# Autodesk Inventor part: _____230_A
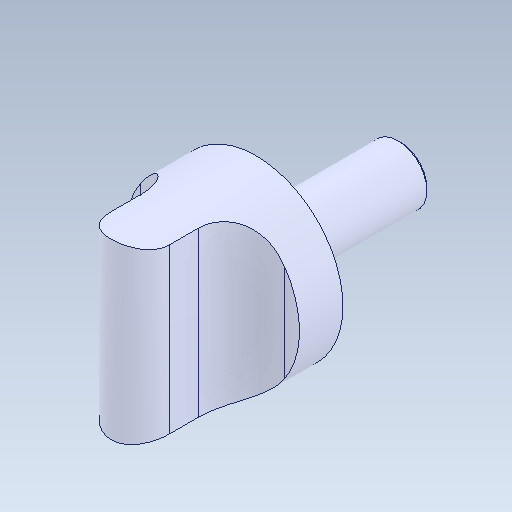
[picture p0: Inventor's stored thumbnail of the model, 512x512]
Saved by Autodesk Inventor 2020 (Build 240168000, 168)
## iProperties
Created: 2017-09
Part Number: _____230_A
Material: Générique
Document SubType Name: Modeling
Designer: bruno
Density: 1 g/cm^3
Appearance: Par défaut
Mass: 0.815785 g
Surface Area: 6.34626 cm^2
Volume: 0.815785 cm^3
Sending System: SolidWorks 2016
Author: bruno
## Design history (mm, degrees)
feature "Importée1"
node "Solide1"
